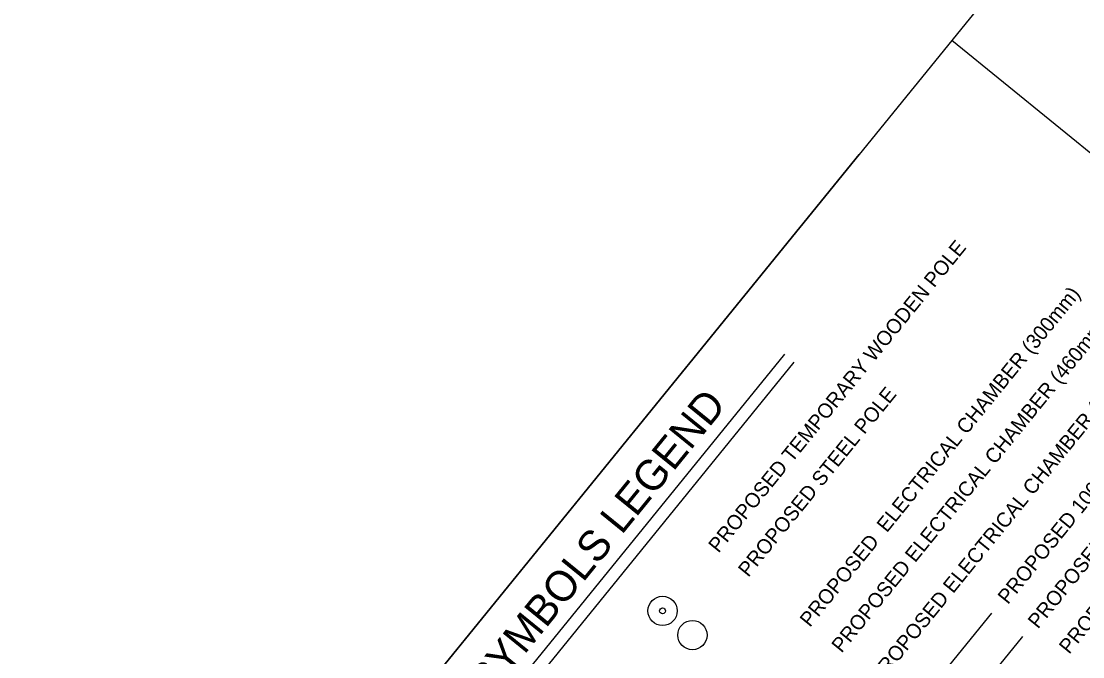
# Model space of a CAD drawing. Extents: x 592613 to 600223, y 4837996 to 4840103.
# Drawn here: x 592902.3 to 592933.72, y 4839286.58 to 4839305.4 of the extents above; entities that cross this region are included whole.
import ezdxf

# ---------------------------------------------------------------- set-up
doc = ezdxf.new("R2010")
doc.units = 0
for name, color, linetype in [('ENG_BORDER', 7, 'Continuous'), ('TCS_100mm-NEW', 7, 'Continuous'), ('TCS_75mm-NEW', 7, 'Continuous'), ('TCS_LEGEND', 7, 'Continuous'), ('TCS_POLE-NEW', 7, 'Continuous')]:
    doc.layers.add(name, color=color, linetype=linetype)

msp = doc.modelspace()

# ---------------------------------------------------------------- linework, layer by layer
at = {"layer": 'ENG_BORDER'}
msp.add_line((593034.225, 4839220.017), (592929.842, 4839304.827), dxfattribs=at)
msp.add_lwpolyline([(593027.682, 4839425.246), (592902.303, 4839270.934)], dxfattribs=at)
at = {"layer": 'TCS_100mm-NEW'}
msp.add_line((592924.727, 4839280.117), (592931.032, 4839287.878), dxfattribs=at)
at = {"layer": 'TCS_75mm-NEW'}
msp.add_line((592925.638, 4839279.424), (592931.944, 4839287.185), dxfattribs=at)
at = {"layer": 'TCS_LEGEND'}
for p, q in [((592910.384, 4839277.672), (592924.901, 4839295.539)), ((592910.666, 4839277.443), (592925.183, 4839295.31))]:
    msp.add_line(p, q, dxfattribs=at)
msp.add_lwpolyline([(592905.041, 4839274.303), (592927.104, 4839301.458)], dxfattribs=at)
at = {"layer": 'TCS_POLE-NEW'}
for centre, radius in [((592921.285, 4839287.943), 0.434), ((592921.285, 4839287.943), 0.0867), ((592922.167, 4839287.227), 0.434)]:
    msp.add_circle(centre, radius, dxfattribs=at)

# ---------------------------------------------------------------- texts
at = {"layer": 'TCS_LEGEND'}
for s, height, p in [('PROPOSED TEMPORARY WOODEN POLE', 0.43374, (592922.94, 4839289.636)), ('PROPOSED  ELECTRICAL CHAMBER (300mm)', 0.43374, (592925.646, 4839287.437)), ('PROPOSED ELECTRICAL CHAMBER (460mm)', 0.43374, (592926.584, 4839286.675)), ('PROPOSED ELECTRICAL CHAMBER (600mm)', 0.43374, (592927.709, 4839285.76)), ('PROPOSED 100mm RIGID PVC', 0.43374, (592931.504, 4839288.114)), ('TRAFFIC SYMBOLS LEGEND', 0.90363, (592912.749, 4839281.158)), ('PROPOSED STEEL POLE', 0.43374, (592923.821, 4839288.919)), ('PROPOSED 75mm RIGID PVC', 0.43374, (592932.395, 4839287.39)), ('PROPOSED 50mm RIGID PVC', 0.43374, (592933.317, 4839286.641))]:
    msp.add_text(s, height=height, rotation=50.9061, dxfattribs=at).set_placement(p)

doc.saveas('drawing.dxf')
